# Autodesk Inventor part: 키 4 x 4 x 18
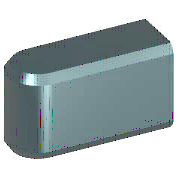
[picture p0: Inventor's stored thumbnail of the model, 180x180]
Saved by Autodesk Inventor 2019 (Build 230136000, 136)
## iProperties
IsCustomPart: 1
Created: 2012-02
Part Number: 키 4 x 4 x 18
Material: 강철, 연강
Description: 키 및 해당 키홈
Document SubType Name: Modeling
Standard: KS B 1311
Designer: mduedu
Standards Organization: KS
Language: ko-KR
Size Designation: 4 x 4 x 18
Categories: <MemberInstance><Categories><Category DisplayName="샤프트 부품" InternalName="7f7aeb1f-a693-4053-b835-cee3144e0d98" Mnemonic="SHFT"><Category DisplayName="키" Interna
Density: 1 g/cm^3
Appearance: 밝은 황색
Author: mduedu
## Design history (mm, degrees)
sketch "스케치1"
  geometry: L1 (2, 2)-(18, 2); L2 (18, 2)-(18, -2); L3 (18, -2)-(2, -2); L4 (0, 7)-(0, -7) reference; L5 (-5, 0)-(30, 0) reference; A1 r 2 centre (2, 0) between (2, 2) and (2, -2)
  constraints: 6 end point, 3 tangent, 2 point on circle, 1 centre point, 1 horizontal, 1 parallel, 1 perpendicular, 1 point on line
  dimensions: "d0" = 2 radius of A1 (= 0.5 x PB); "d7" = 18 distance between parallel lines of L2 L4 (= NLG)
workplane "Work Plane1"
workplane "Work Plane2"
extrude "본체1" new body sketch "스케치1" taper "d3" = 0 deg; stored distance "d4" = 10
workaxis "Work Axis1"
workplane "Work Plane4"
body "Solid1"
chamfer "모따기1" distance "d8" = 0.25 (= PHH); stored, may be unused: second distance "d9" = 0.25 (= PHH), angle "d13" = 45 deg
other parameters: "d1" = -2.5 (= -PNT), "d2" = 1.5 (= PH - PNT), "NLG" = 18 [user parameter; used in 2 equation terms], "PB" = 4 [user parameter; used in 1 equation term], "PNT" = 2.5 [user parameter; used in 2 equation terms], "PH" = 4 [user parameter; used in 1 equation term], "PHH" = 0.25 [user parameter; used in 2 equation terms], "d10" = 0, "d16" = 0, "d17" = 0, "d18" = 0, "RR" = 0.08 [user parameter], "WDMAX" = 12 [user parameter], "PLB1" = 18 (= NLG) [user parameter], "PUEB" = 1.8 [user parameter]
